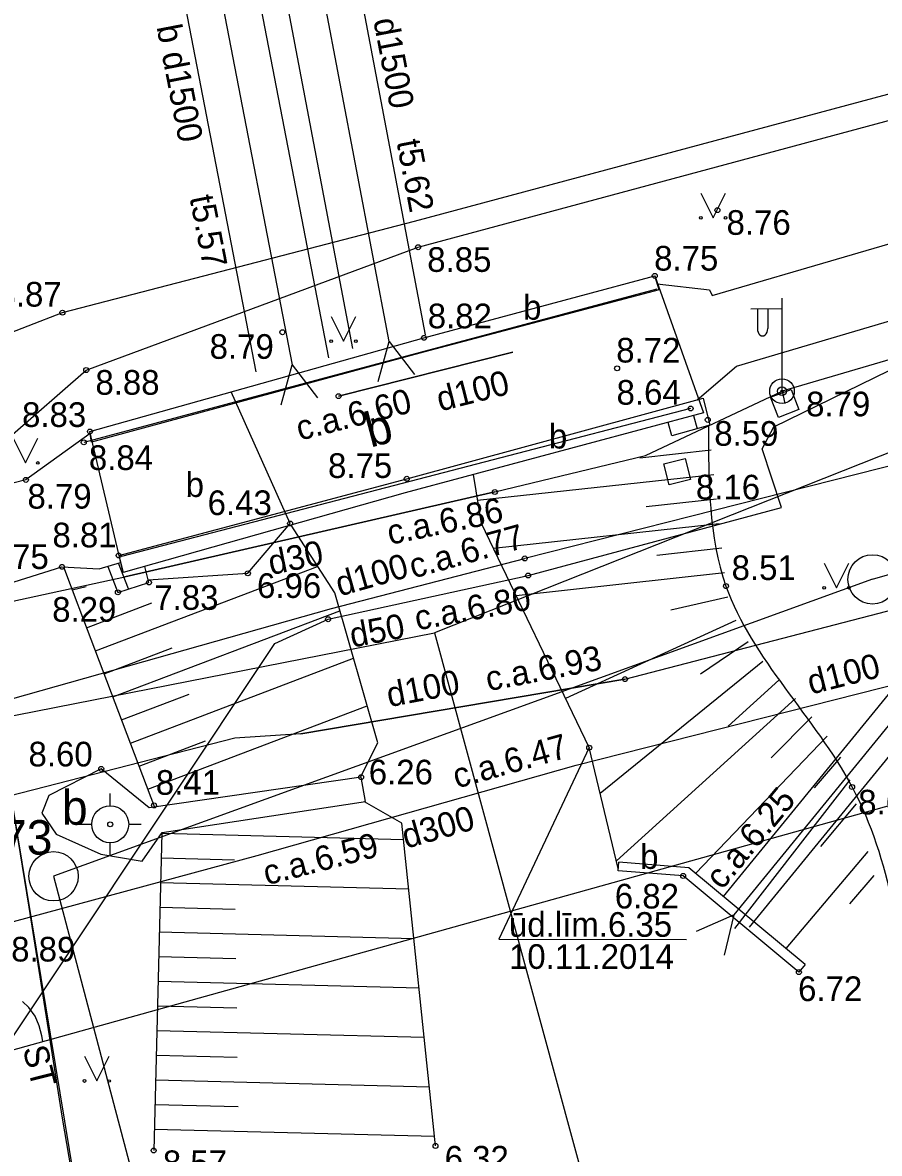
# Model space of a CAD drawing. Extents: x 496078 to 496285, y 304225 to 304369.
# Drawn here: x 496168.49 to 496185.87, y 304288.53 to 304311.46 of the extents above; entities that cross this region are included whole.
import ezdxf

# ---------------------------------------------------------------- set-up
doc = ezdxf.new("R2010")
doc.units = 0
for name, color, linetype in [('APGR_AIZS_####_####_#', 7, 'Continuous'), ('APGR_ELEM_####_####_#', 7, 'Continuous'), ('APGR_SARK_####_####_#', 7, 'Continuous'), ('APGS_ACRL_####_####_#', 7, 'Continuous'), ('APGS_ACRL_####_TKST_#', 7, 'Continuous'), ('APGS_ELEM_####_####_#', 7, 'Continuous'), ('APGS_VADP_ZSPR_####_#', 7, 'Continuous'), ('BUVE_BDET_####_####_#', 7, 'Continuous'), ('BUVE_BDET_####_TKST_#', 7, 'Continuous'), ('CELI_CAPM_####_####_#', 7, 'Continuous'), ('CELI_CMAL_####_####_#', 7, 'Continuous'), ('CELI_CSEG_####_TKST_#', 7, 'Continuous'), ('CKOM_ACRL_####_####_#', 7, 'Continuous'), ('CKOM_ACRL_####_TKST_#', 7, 'Continuous'), ('CKOM_ELEM_####_####_#', 7, 'Continuous'), ('CKOM_VADP_NEDR_####_#', 7, 'Continuous'), ('ELEK_VADP_ZSPR_####_#', 7, 'Continuous'), ('ELEK_VADP_ZSPR_TKST_#', 7, 'Continuous'), ('GEOD_ELEM_####_####_#', 7, 'Continuous'), ('GEOD_ELEM_####_TKST_#', 7, 'Continuous'), ('HIDG_PLIN_####_####_#', 7, 'Continuous'), ('HIDG_UATZ_####_TKST_#', 7, 'Continuous'), ('HIDT_CAUR_####_####_#', 7, 'Continuous'), ('HIDT_CAUR_####_TKST_#', 7, 'Continuous'), ('HIDT_CAUR_KONT_####_#', 7, 'Continuous'), ('HIDT_ELEM_####_####_#', 7, 'Continuous'), ('Level 13', 7, 'Continuous'), ('Level 21', 7, 'Continuous'), ('Level 24', 7, 'Continuous'), ('LKAN_ELEM_####_####_#', 7, 'Continuous'), ('LKAN_VADP_PAST_####_#', 7, 'Continuous'), ('LKAN_VADP_PAST_KONT_#', 7, 'Continuous'), ('LKAN_VADP_PAST_TKST_#', 7, 'Continuous'), ('NORB_MARG_MMET_####_#', 7, 'Continuous'), ('RAMI_UZMR_####_####_#', 7, 'Continuous'), ('RELJ_AATZ_####_TKST_#', 7, 'Continuous'), ('RELJ_ELEM_####_####_#', 7, 'Continuous'), ('RELJ_NOGA_####_####_#', 7, 'Continuous'), ('SAKT_ACRL_####_####_#', 7, 'Continuous'), ('SAKT_ACRL_####_TKST_#', 7, 'Continuous'), ('SAKT_VADP_KABE_####_#', 7, 'Continuous'), ('SAKT_VADP_NEDR_####_#', 7, 'Continuous'), ('TERT_ELEM_####_####_#', 7, 'Continuous'), ('TILT_ANOT_####_TKST_#', 7, 'Continuous'), ('TILT_TKAP_####_####_#', 7, 'Continuous'), ('UDTK_ACRL_####_####_#', 7, 'Continuous'), ('UDTK_ACRL_####_TKST_#', 7, 'Continuous'), ('UDTK_VADP_UDEN_####_#', 7, 'Continuous'), ('UDTK_VADP_UDEN_TKST_#', 7, 'Continuous')]:
    doc.layers.add(name, color=color, linetype=linetype)

msp = doc.modelspace()

# ---------------------------------------------------------------- linework, layer by layer
at = {"layer": 'APGR_AIZS_####_####_#'}
msp.add_lwpolyline([(496171.482, 304276.481), (496169.303, 304289.245), (496168.626, 304293.523), (496167.995, 304297.351), (496154.713, 304324.372)], dxfattribs=at)
at = {"layer": 'APGR_ELEM_####_####_#'}
for centre in [(496185.73, 304300.17), (496169.12, 304294.15)]:
    msp.add_circle(centre, 0.5, dxfattribs=at)
at = {"layer": 'APGR_SARK_####_####_#'}
for p, q in [((496185.729, 304300.172), (496197.161, 304303.516)), ((496185.729, 304300.172), (496169.119, 304294.152)), ((496169.119, 304294.152), (496171.616, 304284.732))]:
    msp.add_line(p, q, dxfattribs=at)
at = {"layer": 'APGS_ACRL_####_####_#'}
msp.add_lwpolyline([(496178.071, 304301.942), (496170.565, 304300.222)], dxfattribs=at)
at = {"layer": 'APGS_ELEM_####_####_#'}
for p, q in [((496183.894, 304303.985), (496183.894, 304305.868)), ((496183.894, 304305.652), (496183.259, 304305.647)), ((496183.394, 304305.648), (496183.394, 304305.256)), ((496183.604, 304305.65), (496183.604, 304305.256))]:
    msp.add_line(p, q, dxfattribs=at)
msp.add_lwpolyline([(496184.238, 304303.612), (496183.821, 304303.451), (496183.663, 304303.862), (496184.08, 304304.022)], close=True, dxfattribs=at)
for radius in [0.25, 0.09, 0.0225]:
    msp.add_circle((496183.894, 304303.985), radius, dxfattribs=at)
msp.add_ellipse((496183.499, 304305.256), major_axis=(0, 0.151), ratio=0.695971, start_param=1.570796, end_param=4.712389, dxfattribs=at)
at = {"layer": 'APGS_VADP_ZSPR_####_#'}
for p, q in [((496192.158, 304306.411), (496183.894, 304303.985)), ((496178.071, 304301.942), (496181.123, 304302.679)), ((496170.565, 304300.222), (496178.071, 304301.942)), ((496167.718, 304299.606), (496170.565, 304300.222))]:
    msp.add_line(p, q, dxfattribs=at)
msp.add_lwpolyline([(496181.123, 304302.679), (496183.894, 304303.985), (496183.951, 304303.737)], dxfattribs=at)
at = {"layer": 'BUVE_BDET_####_####_#'}
for p, q in [((496182.1, 304303.492), (496182.174, 304303.223)), ((496170.643, 304299.976), (496170.439, 304300.501))]:
    msp.add_line(p, q, dxfattribs=at)
for points in [[(496181.4, 304306.04), (496181.313, 304306.322)], [(496181.4, 304306.041), (496176.62, 304304.777), (496169.892, 304302.951), (496169.858, 304303.168)], [(496171.041, 304300.16), (496173.061, 304300.293), (496173.922, 304301.303), (496172.721, 304303.97)], [(496170.445, 304300.655), (496176.283, 304302.209), (496182.297, 304303.846)], [(496182.297, 304303.846), (496182.43, 304303.293)], [(496182.43, 304303.293), (496181.659, 304303.081), (496181.583, 304303.353)], [(496170.445, 304300.655), (496170.532, 304300.307)], [(496170.22, 304300.434), (496170.425, 304299.906), (496171.055, 304300.107), (496170.968, 304300.43)], [(496184.364, 304292.361), (496184.236, 304292.207), (496181.89, 304294.157), (496180.57, 304294.263), (496180.584, 304294.436)], [(496184.364, 304292.361), (496182.005, 304294.322), (496180.584, 304294.436)]]:
    msp.add_lwpolyline(points, dxfattribs=at)
at = {"layer": 'CELI_CAPM_####_####_#'}
for points in [[(496182.479, 304305.927), (496193.216, 304309.063)], [(496182.974, 304304.495), (496193.645, 304307.646)]]:
    msp.add_lwpolyline(points, dxfattribs=at)
at = {"layer": 'CELI_CMAL_####_####_#'}
msp.add_line((496182.17, 304303.811), (496182.974, 304304.495), dxfattribs=at)
for points in [[(496169.864, 304303.13), (496168.559, 304302.187), (496166.548, 304301.675), (496165.812, 304304.226), (496169.3, 304305.578), (496176.443, 304307.431), (496192.141, 304311.641)], [(496166.677, 304301.708), (496169.783, 304304.413), (496176.513, 304306.904), (496192.208, 304311.128)], [(496181.362, 304306.164), (496182.425, 304306.042), (496182.479, 304305.927)], [(496158.075, 304283.625), (496157.379, 304289.059), (496158.33, 304290.346), (496159.317, 304291.067), (496164.506, 304292.685), (496164.77, 304293.516), (496166.848, 304294.299), (496166.345, 304297.413), (496166.963, 304299.697), (496169.291, 304300.424), (496170.044, 304300.38), (496170.481, 304300.514)], [(496171.058, 304295.538), (496170.087, 304296.327), (496169.026, 304295.787), (496168.884, 304295.428), (496169.173, 304295.001), (496170.08, 304294.595), (496170.92, 304294.454), (496171.326, 304295.038)], [(496171.326, 304295.038), (496175.45, 304295.665), (496175.359, 304296.159), (496171.058, 304295.538)]]:
    msp.add_lwpolyline(points, dxfattribs=at)
at = {"layer": 'CKOM_ACRL_####_####_#'}
msp.add_lwpolyline([(496178.433, 304304.778), (496174.9, 304303.884)], dxfattribs=at)
at = {"layer": 'CKOM_ELEM_####_####_#'}
msp.add_lwpolyline([(496182.04, 304302.196), (496181.606, 304302.086), (496181.498, 304302.512), (496181.932, 304302.622)], close=True, dxfattribs=at)
at = {"layer": 'CKOM_VADP_NEDR_####_#'}
msp.add_line((496174.9, 304303.884), (496178.433, 304304.778), dxfattribs=at)
at = {"layer": 'ELEK_VADP_ZSPR_####_#'}
for p, q in [((496168.618, 304291.487), (496168.487, 304291.61)), ((496168.75, 304291.315), (496168.618, 304291.487)), ((496168.828, 304291.115), (496168.75, 304291.315)), ((496168.879, 304290.916), (496168.828, 304291.115)), ((496168.902, 304290.798), (496168.879, 304290.916))]:
    msp.add_line(p, q, dxfattribs=at)
at = {"layer": 'GEOD_ELEM_####_####_#'}
for p, q in [((496170.269, 304295.579), (496170.269, 304295.829)), ((496169.644, 304295.204), (496169.894, 304295.204)), ((496170.644, 304295.204), (496170.894, 304295.204)), ((496170.269, 304294.579), (496170.269, 304294.829))]:
    msp.add_line(p, q, dxfattribs=at)
for radius in [0.375, 0.05]:
    msp.add_circle((496170.269, 304295.204), radius, dxfattribs=at)
at = {"layer": 'HIDG_PLIN_####_####_#'}
for points in [[(496180.574, 304294.31), (496179.984, 304296.758), (496177.796, 304301.304), (496177.634, 304302.297)], [(496175.342, 304296.157), (496175.697, 304296.856), (496174.822, 304299.896), (496173.937, 304301.272)], [(496176.867, 304288.683), (496176.184, 304295.228), (496175.426, 304295.661)]]:
    msp.add_lwpolyline(points, dxfattribs=at)
at = {"layer": 'HIDG_UATZ_####_TKST_#'}
msp.add_lwpolyline([(496179.984, 304296.758), (496178.148, 304292.877), (496181.955, 304292.871)], dxfattribs=at)
at = {"layer": 'HIDT_CAUR_####_####_#'}
for p, q in [((496175.928, 304304.99), (496173.664, 304316.879)), ((496171.657, 304316.413), (496173.961, 304304.517))]:
    msp.add_line(p, q, dxfattribs=at)
at = {"layer": 'HIDT_CAUR_KONT_####_#'}
for p, q in [((496176.665, 304305.13), (496174.401, 304317.019)), ((496175.191, 304304.85), (496172.927, 304316.739)), ((496172.393, 304316.556), (496174.697, 304304.66)), ((496170.921, 304316.27), (496173.225, 304304.374))]:
    msp.add_line(p, q, dxfattribs=at)
at = {"layer": 'HIDT_ELEM_####_####_#'}
for points in [[(496175.701, 304304.183), (496175.928, 304304.99), (496176.438, 304304.324)], [(496173.736, 304303.71), (496173.961, 304304.517), (496174.473, 304303.852)]]:
    msp.add_lwpolyline(points, dxfattribs=at)
at = {"layer": 'Level 13'}
msp.add_lwpolyline([(496167.995, 304297.351), (496176.843, 304299.089)], dxfattribs=at)
at = {"layer": 'Level 21'}
for points in [[(496191.531, 304304.907), (496176.843, 304299.089)], [(496176.843, 304299.089), (496181.199, 304283.099)]]:
    msp.add_lwpolyline(points, dxfattribs=at)
at = {"layer": 'Level 24'}
msp.add_lwpolyline([(496170.693, 304281.022), (496167.995, 304297.351)], dxfattribs=at)
at = {"layer": 'LKAN_ELEM_####_####_#'}
for p, q in [((496182.922, 304293.368), (496182.154, 304293.031)), ((496182.731, 304292.551), (496182.922, 304293.368))]:
    msp.add_line(p, q, dxfattribs=at)
at = {"layer": 'LKAN_VADP_PAST_####_#'}
msp.add_line((496182.922, 304293.368), (496191.127, 304303.418), dxfattribs=at)
at = {"layer": 'LKAN_VADP_PAST_KONT_#'}
for p, q in [((496182.708, 304293.738), (496190.817, 304303.671)), ((496183.232, 304293.115), (496191.437, 304303.165))]:
    msp.add_line(p, q, dxfattribs=at)
at = {"layer": 'NORB_MARG_MMET_####_#'}
for p, q in [((496181.355, 304306.051), (496169.733, 304302.947)), ((496182.041, 304303.634), (496170.501, 304300.634))]:
    msp.add_line(p, q, dxfattribs=at)
at = {"layer": 'RAMI_UZMR_####_####_#'}
msp.add_line((496139.922, 304282.712), (496195.979, 304298.352), dxfattribs=at)
at = {"layer": 'RELJ_ELEM_####_####_#'}
for centre in [(496182.584, 304307.655), (496176.513, 304306.904), (496181.313, 304306.322), (496169.3, 304305.578), (496173.761, 304305.18), (496176.633, 304305.066), (496169.783, 304304.413), (496180.55, 304304.449), (496174.9, 304303.884), (496182.041, 304303.634), (496182.388, 304303.403), (496169.858, 304303.168), (496169.733, 304302.947), (496176.283, 304302.209), (496168.559, 304302.187), (496178.071, 304301.942), (496173.917, 304301.302), (496170.44, 304300.654), (496178.676, 304300.594), (496169.291, 304300.424), (496173.061, 304300.293), (496178.745, 304300.248), (496170.425, 304299.906), (496171.055, 304300.107), (496182.758, 304300.034), (496174.688, 304299.362), (496180.709, 304298.148), (496179.984, 304296.758), (496170.087, 304296.327), (496175.359, 304296.159), (496185.315, 304295.959), (496171.158, 304295.587), (496181.89, 304294.157), (496184.236, 304292.207), (496176.867, 304288.683), (496171.151, 304288.591)]:
    msp.add_circle(centre, 0.05, dxfattribs=at)
at = {"layer": 'RELJ_NOGA_####_####_#'}
for p, q in [((496182.401, 304303.286), (496182.4, 304303.285)), ((496182.455, 304302.789), (496181.011, 304302.63)), ((496182.51, 304302.292), (496177.721, 304301.766)), ((496182.565, 304301.795), (496181.139, 304301.638)), ((496182.619, 304301.298), (496178.041, 304300.795)), ((496182.674, 304300.801), (496181.353, 304300.655)), ((496169.322, 304300.422), (496169.323, 304300.423)), ((496169.322, 304300.422), (496169.613, 304299.656)), ((496169.968, 304298.721), (496174.476, 304300.433)), ((496182.728, 304300.303), (496178.501, 304299.839)), ((496169.499, 304299.955), (496169.783, 304300.023)), ((496182.796, 304299.808), (496181.638, 304299.545)), ((496169.613, 304299.656), (496169.614, 304299.656)), ((496169.79, 304299.189), (496171.113, 304299.691)), ((496170.323, 304297.786), (496174.926, 304299.535)), ((496182.958, 304299.337), (496179.504, 304297.755)), ((496183.205, 304298.902), (496182.241, 304298.251)), ((496170.145, 304298.254), (496171.527, 304298.779)), ((496170.678, 304296.852), (496175.204, 304298.57)), ((496183.505, 304298.502), (496180.208, 304295.83)), ((496183.832, 304298.124), (496182.803, 304297.193)), ((496170.5, 304297.319), (496171.87, 304297.839)), ((496184.168, 304297.754), (496180.537, 304294.462)), ((496171.033, 304295.917), (496175.481, 304297.606)), ((496184.5, 304297.38), (496183.673, 304296.553)), ((496184.809, 304296.988), (496182.142, 304294.208)), ((496170.855, 304296.384), (496172.201, 304296.895)), ((496185.077, 304296.566), (496184.549, 304295.945)), ((496185.273, 304296.107), (496182.929, 304293.092)), ((496185.397, 304295.622), (496184.678, 304294.754)), ((496171.315, 304295.022), (496171.151, 304288.591)), ((496171.315, 304295.022), (496176.219, 304294.897)), ((496185.516, 304295.137), (496185.515, 304295.136)), ((496171.302, 304294.522), (496172.793, 304294.484)), ((496185.634, 304294.651), (496183.973, 304292.687)), ((496171.29, 304294.023), (496176.323, 304293.894)), ((496185.753, 304294.165), (496185.262, 304293.591)), ((496171.277, 304293.523), (496172.806, 304293.484)), ((496171.264, 304293.023), (496176.428, 304292.891)), ((496171.251, 304292.523), (496172.82, 304292.483)), ((496171.239, 304292.023), (496176.533, 304291.888)), ((496171.226, 304291.523), (496172.834, 304291.482)), ((496171.213, 304291.024), (496176.637, 304290.885)), ((496171.2, 304290.524), (496172.847, 304290.482)), ((496171.188, 304290.024), (496176.742, 304289.882)), ((496171.175, 304289.524), (496172.861, 304289.481)), ((496171.162, 304289.024), (496176.847, 304288.879))]:
    msp.add_line(p, q, dxfattribs=at)
msp.add_lwpolyline([(496169.613, 304299.656), (496169.634, 304299.601), (496171.17, 304295.554)], dxfattribs=at)
msp.add_spline([(496182.401, 304303.286), (496182.758, 304300.034), (496185.315, 304295.959), (496186.512, 304291.057)], degree=3, dxfattribs=at)
at = {"layer": 'SAKT_ACRL_####_####_#'}
for p, q in [((496174.76, 304299.582), (496178.676, 304300.594)), ((496174.688, 304299.362), (496178.745, 304300.248)), ((496174.138, 304297.038), (496180.709, 304298.148))]:
    msp.add_line(p, q, dxfattribs=at)
at = {"layer": 'SAKT_VADP_KABE_####_#'}
msp.add_lwpolyline([(496167.053, 304289.039), (496173.605, 304298.868), (496174.688, 304299.362), (496178.745, 304300.248), (496183.885, 304301.628), (496183.489, 304302.815), (496183.729, 304303.26), (496186.359, 304304.549), (496192.281, 304306.153)], dxfattribs=at)
at = {"layer": 'SAKT_VADP_NEDR_####_#'}
for p, q in [((496193.172, 304304.273), (496182.035, 304301.441)), ((496182.035, 304301.441), (496178.676, 304300.594)), ((496174.76, 304299.582), (496178.676, 304300.594)), ((496156.74, 304294.499), (496174.76, 304299.582)), ((496180.709, 304298.148), (496186.466, 304299.643)), ((496172.796, 304296.952), (496161.985, 304294.172))]:
    msp.add_line(p, q, dxfattribs=at)
msp.add_lwpolyline([(496180.709, 304298.148), (496174.138, 304297.038), (496172.796, 304296.952)], dxfattribs=at)
at = {"layer": 'TERT_ELEM_####_####_#'}
for p, q in [((496182.25, 304308), (496182.5, 304307.5)), ((496182.5, 304307.5), (496182.75, 304308)), ((496174.75, 304305.5), (496175, 304305)), ((496175, 304305), (496175.25, 304305.5)), ((496168.302, 304303.031), (496168.552, 304302.531)), ((496168.552, 304302.531), (496168.802, 304303.031)), ((496184.75, 304300.5), (496185, 304300)), ((496185, 304300), (496185.25, 304300.5)), ((496169.75, 304290.5), (496170, 304290)), ((496170, 304290), (496170.25, 304290.5))]:
    msp.add_line(p, q, dxfattribs=at)
for centre, radius in [((496182.25, 304307.5), 0.028), ((496182.75, 304307.5), 0.0263), ((496174.75, 304305), 0.028), ((496175.25, 304305), 0.0263), ((496168.801, 304302.53), 0.0263), ((496184.75, 304300), 0.028), ((496185.25, 304300), 0.0263), ((496169.75, 304290), 0.028), ((496170.25, 304290), 0.0263)]:
    msp.add_circle(centre, radius, dxfattribs=at)
at = {"layer": 'TILT_TKAP_####_####_#'}
for p, q in [((496176.633, 304305.066), (496181.313, 304306.322)), ((496181.313, 304306.322), (496182.3, 304303.545)), ((496169.858, 304303.168), (496176.633, 304305.066)), ((496182.3, 304303.545), (496176.25, 304301.927)), ((496170.532, 304300.307), (496169.858, 304303.168)), ((496176.25, 304301.927), (496170.532, 304300.307))]:
    msp.add_line(p, q, dxfattribs=at)
at = {"layer": 'UDTK_ACRL_####_####_#'}
msp.add_lwpolyline([(496173.247, 304294.572), (496179.718, 304296.4)], dxfattribs=at)
at = {"layer": 'UDTK_VADP_UDEN_####_#'}
for p, q in [((496179.718, 304296.4), (496186.699, 304298.174)), ((496173.247, 304294.572), (496179.718, 304296.4)), ((496154.678, 304289.554), (496173.247, 304294.572))]:
    msp.add_line(p, q, dxfattribs=at)

# ---------------------------------------------------------------- texts
at = {"layer": 'APGS_ACRL_####_TKST_#'}
for s, p in [('c.a.6.86', (496175.941, 304300.868)), ('d30', (496173.531, 304300.256))]:
    msp.add_text(s, height=0.5, rotation=11.6063, dxfattribs=at).set_placement(p)
at = {"layer": 'BUVE_BDET_####_TKST_#'}
for p in [(496178.643, 304305.435), (496179.167, 304302.823), (496171.799, 304301.841), (496181.018, 304294.3)]:
    msp.add_text('b', height=0.5, dxfattribs=at).set_placement(p)
at = {"layer": 'CELI_CSEG_####_TKST_#'}
msp.add_text('b', height=0.7, dxfattribs=at).set_placement((496169.29, 304295.195))
at = {"layer": 'CKOM_ACRL_####_TKST_#'}
for s, p in [('d100', (496176.96, 304303.572)), ('c.a.6.60', (496174.111, 304302.98))]:
    msp.add_text(s, height=0.5, rotation=14.2002, dxfattribs=at).set_placement(p)
at = {"layer": 'ELEK_VADP_ZSPR_TKST_#'}
msp.add_text('ST', height=0.5, rotation=284.2117, dxfattribs=at).set_placement((496168.491, 304290.656))
at = {"layer": 'GEOD_ELEM_####_TKST_#'}
msp.add_text(' 8.473', height=0.7, dxfattribs=at).set_placement((496166.494, 304294.588))
at = {"layer": 'HIDG_UATZ_####_TKST_#'}
for s, p in [('ūd.līm.6.35', (496178.357, 304292.923)), ('10.11.2014', (496178.357, 304292.273))]:
    msp.add_text(s, height=0.5, dxfattribs=at).set_placement(p)
at = {"layer": 'HIDT_CAUR_####_TKST_#'}
for s, rotation, p in [('b d1500', 280.7816, (496175.499, 304312.055)), ('b d1500', 280.9613, (496171.207, 304311.373)), ('t5.62', 280.7816, (496176.073, 304309.042)), ('t5.57', 280.9613, (496171.877, 304307.913))]:
    msp.add_text(s, height=0.5, rotation=rotation, dxfattribs=at).set_placement(p)
at = {"layer": 'LKAN_VADP_PAST_TKST_#'}
msp.add_text('c.a.6.25', height=0.5, rotation=50.2814, dxfattribs=at).set_placement((496182.677, 304293.856))
at = {"layer": 'RELJ_AATZ_####_TKST_#'}
for s, p in [(' 8.76', (496182.584, 304307.155)), (' 8.85', (496176.513, 304306.404)), (' 8.75', (496181.115, 304306.43)), (' 8.87', (496167.798, 304305.7)), (' 8.82', (496176.523, 304305.26)), (' 8.79', (496172.1, 304304.641)), (' 8.72', (496180.346, 304304.566)), (' 8.88', (496169.783, 304303.913)), (' 8.64', (496180.353, 304303.711)), (' 8.79', (496184.197, 304303.475)), (' 8.83', (496168.296, 304303.26)), (' 8.59', (496182.335, 304302.878)), (' 8.84', (496169.651, 304302.387)), (' 8.75', (496174.501, 304302.226)), ('8.16', (496182.148, 304301.79)), (' 8.79', (496168.405, 304301.604)), (' 6.43', (496172.059, 304301.473)), (' 8.81', (496168.912, 304300.819)), (' 8.75', (496167.536, 304300.379)), (' 8.51', (496182.686, 304300.156)), (' 6.96', (496173.061, 304299.793)), (' 7.83', (496170.978, 304299.552)), (' 8.29', (496168.907, 304299.311)), (' 8.60', (496168.426, 304296.377)), (' 6.26', (496175.327, 304296.013)), (' 8.41', (496171.009, 304295.802)), (' 8.60', (496185.254, 304295.403)), (' 6.82', (496180.317, 304293.497)), (' 8.89', (496168.075, 304292.422)), (' 6.72', (496184.034, 304291.62)), (' 8.57', (496171.151, 304288.091)), (' 6.32', (496176.867, 304288.183))]:
    msp.add_text(s, height=0.5, dxfattribs=at).set_placement(p)
at = {"layer": 'SAKT_ACRL_####_TKST_#'}
for s, rotation, p in [('c.a.6.77', 15.4281, (496176.412, 304300.185)), ('d100', 15.7789, (496174.923, 304299.822)), ('c.a.6.80', 10.4055, (496176.492, 304299.134)), ('d50', 10.7549, (496175.178, 304298.786)), ('c.a.6.93', 10.7708, (496177.934, 304297.901)), ('d100', 10.7708, (496175.927, 304297.578))]:
    msp.add_text(s, height=0.5, rotation=rotation, dxfattribs=at).set_placement(p)
at = {"layer": 'TILT_ANOT_####_TKST_#'}
msp.add_text('b', height=0.7, rotation=14.8121, dxfattribs=at).set_placement((496175.546, 304302.839))
at = {"layer": 'UDTK_ACRL_####_TKST_#'}
for s, rotation, p in [('c.a.6.47', 15.6448, (496177.297, 304295.927)), ('d300', 15.8537, (496176.269, 304294.707)), ('c.a.6.59', 14.536, (496173.444, 304293.965))]:
    msp.add_text(s, height=0.5, rotation=rotation, dxfattribs=at).set_placement(p)
at = {"layer": 'UDTK_VADP_UDEN_TKST_#'}
msp.add_text('d100', height=0.5, rotation=14.1182, dxfattribs=at).set_placement((496184.48, 304297.833))

doc.saveas('drawing.dxf')
